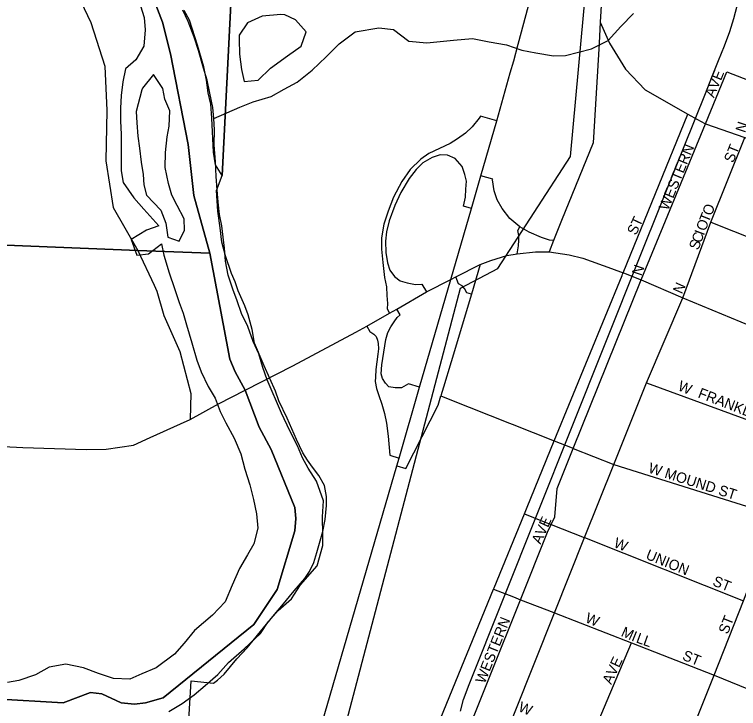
# Model space of a CAD drawing. Extents: x 1643459 to 2064572, y 425441 to 780708.
# Drawn here: x 1839127 to 1842601, y 582083 to 585413 of the extents above; entities that cross this region are included whole.
import ezdxf

# ---------------------------------------------------------------- set-up
doc = ezdxf.new("R2010")
doc.units = 0
for name, color, linetype in [('GM_X_Airport_Class_2', 7, 'Continuous'), ('GM_X_Airport_Class_3', 7, 'Continuous'), ('GM_X_City_Street', 7, 'Continuous'), ('GM_X_Minor_Lake', 7, 'Continuous'), ('GM_X_Rail_Line_Text', 7, 'Continuous'), ('GM_X_Section', 7, 'Continuous'), ('GM_X_State_Route', 7, 'Continuous'), ('GM_X_Township_Road', 7, 'Continuous'), ('GM_X_Township_Subdivision_Text', 7, 'Continuous'), ('GM_X_Unincorporated_Text', 7, 'Continuous'), ('GM_X_US_Route', 7, 'Continuous'), ('MT_P_Cells', 7, 'Continuous'), ('RD_X_Wall', 7, 'Continuous')]:
    doc.layers.add(name, color=color, linetype=linetype)

msp = doc.modelspace()

# ---------------------------------------------------------------- linework, layer by layer
at = {"layer": 'GM_X_Airport_Class_2'}
for points in [[(1841938.1, 585377), (1841981.8, 585275.7), (1842059.4, 585150.9), (1842153.1, 585052), (1842358.5, 584935.5), (1842404, 584909.7)], [(1842134.5, 584139.7), (1842443.1, 584888.5), (1842545.7, 585137.4)], [(1842545.7, 585137.4), (1842729.9, 585065.8)], [(1842042.3, 584161.2), (1842044.8, 584167.3), (1842047.7, 584174.4), (1842358.5, 584935.5)], [(1842404, 584909.7), (1842404.7, 584909.3), (1842438.9, 584889.9), (1842443.1, 584888.5), (1842631, 584822.6), (1843393, 584507.8)], [(1842334.2, 584053.5), (1842468.4, 584416.4), (1842631, 584822.6)], [(1842468.4, 584416.4), (1843230.1, 584114.5)], [(1841361.7, 584212.9), (1841319.4, 584071.5), (1841222, 583745.8)], [(1841262.7, 581777.3), (1841259.7, 581788.3), (1841260.3, 581870.6), (1841555.3, 582605.2), (1841685.2, 582928.8), (1841702.7, 582966.3), (1841719.8, 583002.7), (1841730.9, 583139.1), (1841808.4, 583331.3), (1842134.5, 584139.7)], [(1841586.6, 583048.6), (1841717.1, 583367.3), (1842042.3, 584161.2)], [(1842003.2, 583254.4), (1842159.8, 583645.7), (1842334.2, 584053.5)], [(1841174.5, 578817.5), (1841179.6, 578835.6), (1841328.3, 579252.1), (1841368.4, 579377.4), (1841432.7, 579578.5), (1841587.1, 579969.8), (1841727.7, 580326.4), (1841807.1, 580527.6), (1841898.6, 580759.7), (1841926.3, 580830.1), (1842100.9, 581299.2), (1842297.2, 581776.6), (1842483.5, 582242.9), (1842624.4, 582600), (1842782.2, 583008.4), (1842924.7, 583366.4), (1843082.5, 583766.7)], [(1841222, 583745.8), (1841186, 583625.5), (1841173.3, 583582.9)], [(1842159.8, 583645.7), (1842924.7, 583366.4)], [(1841173.3, 583582.9), (1841215.8, 583565.1), (1841501.6, 583452.3), (1841514.8, 583447.1)], [(1841514.8, 583447.1), (1841717.1, 583367.3), (1841802.6, 583333.6), (1841807.9, 583331.5)], [(1841807.9, 583331.5), (1841808.4, 583331.3), (1842003.2, 583254.4), (1842782.2, 583008.4)], [(1841291.1, 581475.5), (1841330.1, 581572.8), (1841525.6, 582061.2), (1841718, 582541.7), (1841862.5, 582902.8), (1842003.2, 583254.4)], [(1841428.3, 582661.5), (1841573.9, 583017.4), (1841586.6, 583048.5), (1841586.6, 583048.6)], [(1841573.9, 583017.4), (1841669.4, 582979.5)], [(1841669.4, 582979.5), (1841669.4, 582979.5), (1841702.7, 582966.3), (1841860.4, 582903.6)], [(1841860.4, 582903.6), (1841862.5, 582902.8), (1842624.4, 582600)], [(1841032.5, 581693.8), (1841426, 582655.8), (1841428.3, 582661.5), (1841428.3, 582661.5)], [(1841426, 582655.8), (1841522.1, 582618.2), (1841522.1, 582618.2)], [(1841522.1, 582618.2), (1841555.3, 582605.2), (1841714.4, 582543.2), (1841714.4, 582543.1)], [(1841714.4, 582543.1), (1841718, 582541.7), (1842087.2, 582397.6), (1842483.5, 582242.9)], [(1841877.5, 581898.4), (1841877.5, 581898.4), (1841885.1, 581916.4), (1842087.2, 582397.6)], [(1842483.5, 582242.9), (1843241.4, 581934.8), (1843703.6, 581746.9), (1844556.3, 581400.2), (1844562.5, 581399.1), (1844602.8, 581391.9), (1844603.1, 581391.8)]]:
    msp.add_lwpolyline(points, dxfattribs=at)
at = {"layer": 'GM_X_City_Street'}
for points in [[(1839806, 585459.2), (1839837.5, 585376.7), (1839876.6, 585224), (1839960, 584790), (1839988.5, 584544.9), (1840063.9, 584267.8), (1839718.5, 584280), (1831304.5, 584621.8)], [(1839031.5, 582128.8), (1839361.5, 582110.6), (1839491.9, 582160), (1839545.9, 582153.6), (1839639.7, 582110.9), (1839703.6, 582104.4), (1839755.7, 582110.1), (1839839.9, 582133.6), (1840276.2, 582486.1), (1840387.3, 582653.9), (1840473, 582936.3), (1840477.4, 582994.5), (1840471.7, 583046.7), (1840359.3, 583326.4), (1840302, 583433.1), (1840234, 583610.1), (1840185.5, 583698.8), (1840159.9, 583759.2), (1840063.9, 584267.8), (1839988.5, 584544.9), (1839960, 584790), (1839876.6, 585224), (1839837.5, 585376.7), (1839806, 585459.2)], [(1831304.5, 584621.8), (1839718.5, 584280), (1840063.9, 584267.8), (1840159.9, 583759.2), (1840185.5, 583698.8), (1840234, 583610.1), (1840302, 583433.1), (1840359.3, 583326.4), (1840471.7, 583046.7), (1840477.4, 582994.5), (1840473, 582936.3), (1840387.3, 582653.9), (1840276.2, 582486.1), (1839839.9, 582133.6), (1839755.7, 582110.1), (1839703.6, 582104.4), (1839639.7, 582110.9), (1839545.9, 582153.6), (1839491.9, 582160), (1839361.5, 582110.6), (1839031.5, 582128.8)]]:
    msp.add_lwpolyline(points, dxfattribs=at)
at = {"layer": 'GM_X_Minor_Lake'}
for points in [[(1841977, 586042), (1841938.1, 585377)], [(1841938.1, 585377), (1841932.2, 585275.3), (1841932.1, 585273.7)], [(1841932.1, 585273.7), (1841904.3, 584797), (1841752.3, 584424.8)], [(1841752.3, 584424.8), (1841713.2, 584329), (1841693.4, 584274)]]:
    msp.add_lwpolyline(points, dxfattribs=at)
at = {"layer": 'GM_X_Rail_Line_Text'}
msp.add_lwpolyline([(1839871.3, 573785.7), (1839694.5, 578583.6), (1839774.5, 578586.5), (1839764.4, 578860.3), (1839810.1, 579262.8), (1840033.5, 579270.8), (1840084, 579366), (1840444.1, 579218.3), (1840503.9, 578841.4), (1840741.5, 578829.6), (1840529.8, 579626.8), (1840486.7, 579896.2), (1840414.9, 580812.1), (1840440.1, 581094.8), (1840575, 581480.5), (1840665, 581806.6), (1841266.6, 584100.1), (1841447.1, 584195.1), (1841794.2, 584731.1), (1841983.4, 586786.3)], dxfattribs=at)
at = {"layer": 'GM_X_Section'}
for points in [[(1837582.6, 588421.2), (1837623.2, 588406.5), (1837905.9, 588304.5), (1837973.3, 588241.5), (1838022.3, 588144.7), (1838168.6, 587445), (1838239.8, 587018.9), (1838343, 586576.4), (1838517.9, 586277.5), (1838706, 586086.7), (1838879, 585970.3), (1839099.9, 585843.3), (1839304.8, 585710.4), (1839399.4, 585574.9), (1839493.3, 585375.3), (1839561, 585165.9), (1839570.6, 584953.1), (1839565.8, 584710.5), (1839601.4, 584487.4), (1839718.5, 584280), (1839797.2, 584114.7)], [(1839797.2, 584114.7), (1839810.9, 584085.9), (1839843.8, 583968.2), (1839920, 583795.6), (1839973.8, 583594.4), (1839969.6, 583470.4)]]:
    msp.add_lwpolyline(points, dxfattribs=at)
at = {"layer": 'GM_X_State_Route'}
for points in [[(1839938.5, 581595.9), (1839975.5, 582215.7), (1840081.4, 582205.2), (1840101.5, 582219.1), (1840133.6, 582246.9), (1840194, 582320.6), (1840244.2, 582374.4), (1840322.7, 582470), (1840383.1, 582543.7), (1840409.2, 582575.6), (1840469.6, 582647.3), (1840519.9, 582707.1), (1840542, 582741), (1840564.2, 582782.9), (1840578.5, 582830.8), (1840606.9, 582932.7), (1840617.2, 582990.6), (1840623.5, 583056.6), (1840623.8, 583100.6), (1840614, 583152.6), (1840588.2, 583200.8), (1840556.4, 583240.9), (1840532.6, 583275), (1840510.7, 583309.1), (1840481.1, 583373.3), (1840435.5, 583475.5), (1840395.9, 583559.7), (1840380.2, 583605.8), (1840324.7, 583728), (1840279.2, 583836.3), (1840267.6, 583902.3), (1840247.9, 583972.4), (1840232.1, 584014.5), (1840200.4, 584086.6), (1840186.7, 584130.7), (1840168.8, 584170.8), (1840139.3, 584254.9), (1840121.6, 584321), (1840113.9, 584389.1), (1840102.3, 584469.2), (1840096.8, 584569.2), (1840123.1, 584641), (1840240.2, 586952.6)], [(1840240.2, 586952.6), (1840123.1, 584641), (1840091.3, 584691.2), (1840081.6, 584753.2), (1840074.4, 584915.3), (1840068.8, 584983.3), (1840057, 585037.4), (1840049.3, 585097.4), (1840035.6, 585161.5), (1840006.1, 585265.6), (1839966.7, 585385.8), (1839940.9, 585431.9)]]:
    msp.add_lwpolyline(points, dxfattribs=at)
at = {"layer": 'GM_X_Township_Road'}
msp.add_lwpolyline([(1841266.9, 582069.7), (1841281.8, 582125.4), (1841309.4, 582198.8), (1842126, 584246.3), (1842339.6, 584779.3), (1842442.2, 585033.7), (1842473.1, 585113.1), (1842505.1, 585193.1), (1842533.2, 585263.2), (1842559.1, 585331.1), (1842579, 585394), (1842595, 585454.7)], dxfattribs=at)
at = {"layer": 'GM_X_Township_Subdivision_Text'}
for points in [[(1840205, 585313.4), (1840204.8, 585293.3), (1840206.4, 585223.1), (1840216, 585148.7), (1840229.6, 585092.5), (1840295.7, 585098.1), (1840356.1, 585155.9), (1840436.5, 585215.6), (1840502.8, 585261.3), (1840527.2, 585329.4), (1840475.6, 585387.9), (1840423.7, 585412.3), (1840405.6, 585413.1)], [(1840405.6, 585413.1), (1840315.6, 585405), (1840245.3, 585373.3), (1840205, 585313.4)]]:
    msp.add_lwpolyline(points, dxfattribs=at)
at = {"layer": 'GM_X_Unincorporated_Text'}
for points in [[(1839731.6, 585454.9), (1839749.3, 585398.6), (1839754.9, 585340.3), (1839748.4, 585262.1), (1839710, 585196.1), (1839659.7, 585152.3), (1839647.3, 585090.2), (1839638.9, 585024), (1839636.6, 584963.8), (1839636.2, 584901.6), (1839639.8, 584839.4), (1839639.4, 584773.1), (1839638.7, 584662.8), (1839648.4, 584606.5), (1839700, 584533.9), (1839747.7, 584479.4), (1839819.2, 584398.7), (1839761.1, 584379), (1839686.8, 584333.3), (1839714.3, 584258.9), (1839770.4, 584264.6), (1839832.7, 584312.3), (1839844.4, 584258.1), (1839869.9, 584173.6), (1839895.5, 584099.2), (1839917.1, 584030.8), (1839936.8, 583980.5), (1839952.4, 583924.2), (1839977.9, 583837.8)], [(1839867.2, 582068.4), (1839931.4, 582106.2), (1839989.7, 582147.9), (1840042, 582193.8), (1840102.4, 582245.5), (1840154.7, 582303.4), (1840229.2, 582369.2), (1840307.6, 582442.9), (1840344, 582498.8), (1840392.4, 582552.7), (1840456.7, 582608.5), (1840499.2, 582676.5), (1840579.8, 582768.3), (1840606.4, 582864.4), (1840606.7, 582918.6), (1840605.2, 583002.9), (1840609.6, 583079.1), (1840576.2, 583173.7), (1840536.6, 583236.1), (1840508.9, 583286.5), (1840485.2, 583342.8), (1840447.6, 583415.3), (1840408.1, 583499.9), (1840339, 583660.9), (1840319.4, 583719.2), (1840299.8, 583785.5), (1840272.1, 583843.9), (1840246.5, 583916.3), (1840216.9, 583978.7), (1840195.2, 584039.1), (1840175.6, 584095.4), (1840152, 584161.8), (1840140.4, 584230.1), (1840134.8, 584292.3), (1840129.1, 584344.5), (1840121.4, 584398.8), (1840111.7, 584453), (1840104.1, 584513.3), (1840100.4, 584571.5), (1840094.8, 584635.8), (1840091.2, 584706), (1840085.7, 584788.3), (1840086.2, 584860.6), (1840084.5, 584914.8), (1840078.8, 584967), (1840065.2, 585035.3), (1840051.6, 585097.6), (1840033.9, 585155.9), (1840010.4, 585240.4), (1839988.8, 585304.7), (1839961.2, 585379.2), (1839935.6, 585433.5)], [(1839738.1, 585051.9), (1839710.5, 584947.3), (1839714.2, 584893.1), (1839719.8, 584828.8), (1839727.5, 584772.6), (1839735, 584704.3), (1839744.7, 584646), (1839748.4, 584595.8), (1839760.1, 584545.6), (1839829.7, 584474.9), (1839853.3, 584412.5), (1839862.9, 584344.2), (1839916.8, 584325.8), (1839943.2, 584377.8), (1839941.5, 584432), (1839907.9, 584496.5), (1839882.2, 584546.8), (1839866.5, 584603.1), (1839850.9, 584679.5), (1839851.4, 584751.7), (1839859.8, 584825.9), (1839870.2, 584878), (1839872.6, 584950.3), (1839848.9, 585006.6), (1839839.2, 585058.8), (1839793.6, 585125.4)], [(1839793.6, 585125.4), (1839741.2, 585059.5), (1839738.1, 585051.9)], [(1839977.9, 583837.8), (1840001.4, 583755.3), (1840023.1, 583699), (1840056.7, 583628.6), (1840090.4, 583572.2), (1840114, 583507.8), (1840141.7, 583453.4), (1840181.3, 583380.9), (1840212.8, 583304.4), (1840232.4, 583232.1), (1840255.9, 583155.7), (1840273.5, 583085.3), (1840289.1, 583017), (1840294.7, 582948.7), (1840276.2, 582872.6), (1840245.9, 582820.6), (1840207.5, 582754.6), (1840171, 582674.6), (1840138.5, 582594.5), (1840078.1, 582530.7), (1839991.6, 582457), (1839941.2, 582397.1), (1839894.8, 582343.2), (1839806.4, 582277.5), (1839738.2, 582249.9), (1839680, 582224.2), (1839602, 582226.7), (1839530.1, 582251.2), (1839458.2, 582277.8), (1839374.3, 582296.4), (1839294.2, 582280.8), (1839227.9, 582245.1), (1839147.7, 582217.5), (1839093.6, 582207.9)]]:
    msp.add_lwpolyline(points, dxfattribs=at)
at = {"layer": 'GM_X_US_Route'}
msp.add_lwpolyline([(1840084.5, 584914.8), (1840208.9, 584968.2), (1840273.1, 584993.8), (1840359.3, 585019.4), (1840421.5, 585055.1), (1840483.7, 585088.8), (1840556.1, 585146.6), (1840622.5, 585210.3), (1840685, 585272.2), (1840761.3, 585329.9), (1840875.5, 585349.2), (1840945.5, 585340.7), (1841019.2, 585286.1), (1841105.2, 585277.5), (1841169.3, 585283.1), (1841233.4, 585290.7), (1841325.4, 585298.2), (1841405.4, 585281.6), (1841487.3, 585267), (1841561.2, 585242.4), (1841629.2, 585230), (1841713.1, 585215.4), (1841771.2, 585217), (1841895.4, 585248.3), (1841975.7, 585287.9), (1842036.2, 585355.8), (1842096.6, 585417.6)], dxfattribs=at)
at = {"layer": 'MT_P_Cells'}
for points in [[(1841441.8, 584902.6), (1841363.2, 584925.7), (1841356.7, 584916.1), (1841322.4, 584874.7), (1841291.2, 584844), (1841252.3, 584817.1), (1841217.4, 584793.5), (1841166.3, 584770.3), (1841115.2, 584747), (1841077.3, 584718.4), (1841026.2, 584670), (1840985.3, 584611.3), (1840945.8, 584537.4), (1840920, 584469.9), (1840899.9, 584406.5), (1840888.3, 584342.1), (1840888.4, 584287.5), (1840894.3, 584222.5), (1840903.1, 584152), (1840911.9, 584106.7), (1840914.2, 584064.7), (1840916.5, 584027.2), (1840914.7, 584001.2), (1840927.3, 583980.2)], [(1841319.7, 584481.9), (1841282.2, 584492.9), (1841290.9, 584537.5), (1841293.1, 584575.2), (1841295.8, 584614.2), (1841288.8, 584645.7), (1841275, 584683.7), (1841241.9, 584721.5), (1841205.5, 584738.1), (1841169.2, 584739.9), (1841131.6, 584727.4), (1841086.8, 584700.8), (1841055.3, 584668.8), (1841020.6, 584626), (1840980.4, 584559.7), (1840951.7, 584497.4), (1840925.3, 584422.6), (1840912.8, 584370.3), (1840906.8, 584324.9), (1840908.7, 584271.3), (1840916.3, 584221.9), (1840927.8, 584186), (1840950, 584156), (1840977.6, 584134.5), (1841011.9, 584125.9), (1841050.7, 584117.4), (1841081.2, 584119.1), (1841103.4, 584081.7)], [(1841713.2, 584329), (1841694.3, 584330.3), (1841655.4, 584343.2), (1841596.7, 584369.3), (1841552.6, 584394), (1841504, 584435), (1841466.5, 584482.9), (1841443.1, 584523.7), (1841428.1, 584567.9), (1841421.3, 584620), (1841421.6, 584622.7), (1841365.4, 584639.2)], [(1841538.9, 584264.1), (1841544.9, 584303.5), (1841547.5, 584331), (1841546.7, 584352.7), (1841542.7, 584376.4), (1841552.6, 584394)], [(1841319.4, 584071.5), (1841296.9, 584077.3), (1841286.8, 584098), (1841276, 584111.5), (1841258.2, 584121.2), (1841245.4, 584153.9)], [(1841071.2, 583624.5), (1841017.3, 583640.4), (1840984.5, 583622.5), (1840953.2, 583621.4), (1840923.9, 583627.1), (1840906.8, 583643.9), (1840893, 583667.1), (1840886.3, 583689.7), (1840889.8, 583731.5), (1840908.3, 583854.3), (1840917.9, 583886.8), (1840933.4, 583914.6), (1840949.2, 583938), (1840964.1, 583958.7), (1840978.2, 583971.7), (1840961.5, 583999.8)], [(1840817.9, 583917.5), (1840832.6, 583892.8), (1840850.6, 583878.6), (1840862.1, 583867.9), (1840869, 583851.1), (1840872.8, 583833.8), (1840874.5, 583809.7), (1840871, 583782.7), (1840861, 583709), (1840859.2, 583672.7), (1840857.7, 583652.5), (1840863.8, 583618.3), (1840874.8, 583585.5), (1840890.2, 583542.7), (1840902.1, 583497.9), (1840912.2, 583452.2), (1840920.3, 583389.4), (1840927.5, 583298.2), (1840972.8, 583284.9)], [(1840961.7, 583246.9), (1841004.6, 583234.3), (1841159.6, 583538.1), (1841173.3, 583582.9)]]:
    msp.add_lwpolyline(points, dxfattribs=at)
at = {"layer": 'RD_X_Wall'}
for points in [[(1841522.5, 585191.7), (1841544.6, 585271.2), (1841694.5, 585831.3), (1841780.3, 586116.7)], [(1841506.3, 585133.9), (1841522.5, 585191.7)], [(1841221, 584141.6), (1841319.7, 584481.9), (1841365.4, 584639.2), (1841441.8, 584902.6), (1841506.3, 585133.9)], [(1841538.9, 584264.1), (1841627.8, 584274), (1841693.4, 584274)], [(1841693.4, 584274), (1841787.8, 584259.6), (1841854.7, 584243.8), (1841991.1, 584194.7)], [(1841221, 584141.6), (1841221, 584141.6), (1841245.4, 584153.9), (1841361.7, 584212.9), (1841412.2, 584233.5), (1841490.3, 584256), (1841538.9, 584264.1)], [(1841991.1, 584194.7), (1842047.7, 584174.4), (1842049.6, 584173.7), (1842134.5, 584139.7), (1842334.2, 584053.5), (1842751.1, 583881.5)], [(1840432.6, 581315.4), (1840441.5, 581365.5), (1840576.6, 581922), (1840961.7, 583246.9), (1840972.8, 583284.9), (1841071.2, 583624.5), (1841221, 584141.6)], [(1840927.3, 583980.2), (1840961.5, 583999.8), (1841103.4, 584081.7), (1841221, 584141.6)], [(1840817.9, 583917.5), (1840817.9, 583917.5), (1840927.3, 583980.2)], [(1840765, 583889.3), (1840817.9, 583917.5)], [(1839923, 583449), (1839969.6, 583470.4), (1840106.5, 583544.3), (1840234, 583610.1), (1840462.4, 583727.9), (1840765, 583889.3)], [(1838460.1, 583375.6), (1838513.1, 583369), (1839167.4, 583336.2), (1839471.3, 583325.2), (1839567.2, 583328), (1839698.6, 583347.1), (1839777.9, 583382.7), (1839923, 583449)]]:
    msp.add_lwpolyline(points, dxfattribs=at)

# ---------------------------------------------------------------- texts
at = {"layer": 'GM_X_Airport_Class_3'}
for s, rotation, p in [('AVE', 67.838, (1842483.1, 585010.4)), ('N', 71.5723, (1842632.5, 584842.6)), ('ST', 68.1961, (1842575.5, 584697.9)), ('WESTERN', 67.7134, (1842263.1, 584469.2)), ('O', 67.4356, (1842470.7, 584443.8)), ('ST', 64.9823, (1842109.3, 584350.8)), ('T', 68.1326, (1842457.7, 584411.2)), ('O', 69.2905, (1842442.2, 584370.3)), ('I', 69.4081, (1842434.5, 584349.8)), ('C', 69.441, (1842420.6, 584312.7)), ('S', 69.4216, (1842408.2, 584279.7)), ('N', 71.5578, (1842135.3, 584156.2)), ('N', 66.0555, (1842329.3, 584069)), ('W', 337.3931, (1842306.2, 583611.9)), ('FRANKLIN', 338.8598, (1842402.8, 583576.8)), ('W MOUND ST', 342.3773, (1842164.7, 583216.2)), ('E', 65.4633, (1841686.8, 582948.2)), ('V', 66.3393, (1841669.2, 582908.1)), ('A', 66.3594, (1841651.6, 582867.8)), ('W', 337.3776, (1841998.3, 582859.5)), ('UNION', 337.6209, (1842152.2, 582802.4)), ('ST', 338.1961, (1842473.3, 582674.8)), ('W', 337.3776, (1841861.8, 582498.7)), ('WESTERN', 68.1986, (1841383.1, 582198.7)), ('ST', 68.1961, (1842549.1, 582436.3)), ('M', 335.6344, (1842033.9, 582432.5)), ('I', 338.0166, (1842084, 582409.9)), ('L', 340.0741, (1842106.2, 582400.9)), ('L', 340.3406, (1842139.6, 582388.9)), ('AVE', 65.2307, (1841990.5, 582194.8)), ('ST', 338.1961, (1842328.1, 582318.4)), ('W', 337.3776, (1841540.6, 582071.9))]:
    msp.add_text(s, height=50, rotation=rotation, dxfattribs=at).set_placement(p)

doc.saveas('drawing.dxf')
